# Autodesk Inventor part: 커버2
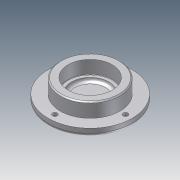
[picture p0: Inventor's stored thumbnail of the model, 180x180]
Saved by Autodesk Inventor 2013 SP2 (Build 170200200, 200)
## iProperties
Company: 한국ATC센터
Created: 2014-10
Part Number: 커버2
Document SubType Name: Modeling
Designer: KYOUNG IL JANG
Density: 1 g/cm^3
Mass: 44.7286 g
Surface Area: 161.165 cm^2
Volume: 44.7286 cm^3
Material: 일반
Author: KYOUNG IL JANG
Revision Number: 1
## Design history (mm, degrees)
sketch "스케치1"
  geometry: C1 r 38 at (0, 0); 1 further point
  constraints: 1 centre point, 1 coincident
  dimensions: "d0" = 76 diameter of C1
extrude "돌출1" new body sketch "스케치1" distance "d1" = 7; taper "d2" = 0 deg
sketch "스케치2"
  geometry: C1 r 27 at (0, 0); 1 further point
  constraints: 1 centre point, 1 coincident
  dimensions: "d3" = 54 diameter of C1
extrude "돌출2" join sketch "스케치2" distance "d4" = 13; taper "d5" = 0 deg
hole "구멍2" diameter "d20" = 34; stored, may be unused: countersink angle "d24" = 90 deg, drill point angle "d26" = 0 deg; dims "d18" = 10, "d19" = 10, "d21" = 6, "d22" = 40, "d23" = 12, "d25" = 3
fillet "모깎기2" dims "d34" = 3
fillet "모깎기1" dims "d27" = 0.3
chamfer "모따기1" distance "d28" = 1; stored, may be unused: second distance "d29" = 2, angle "d30" = 45 deg
sketch "스케치4" dims "d35" = 64
  geometry: 3 further points
  constraints: 2 horizontal alignment, 1 coincident, 2 other
hole "구멍3" sketch "스케치4" at (32, 0) diameter "d36" = 4.5; stored, may be unused: countersink angle "d40" = 90 deg, drill point angle "d42" = 118 deg; dims "d37" = 6, "d38" = 8, "d39" = 4.4, "d41" = 13
node "솔리드1"
pattern_circular "원형 패턴1" dims angle "d44" = 360 deg
